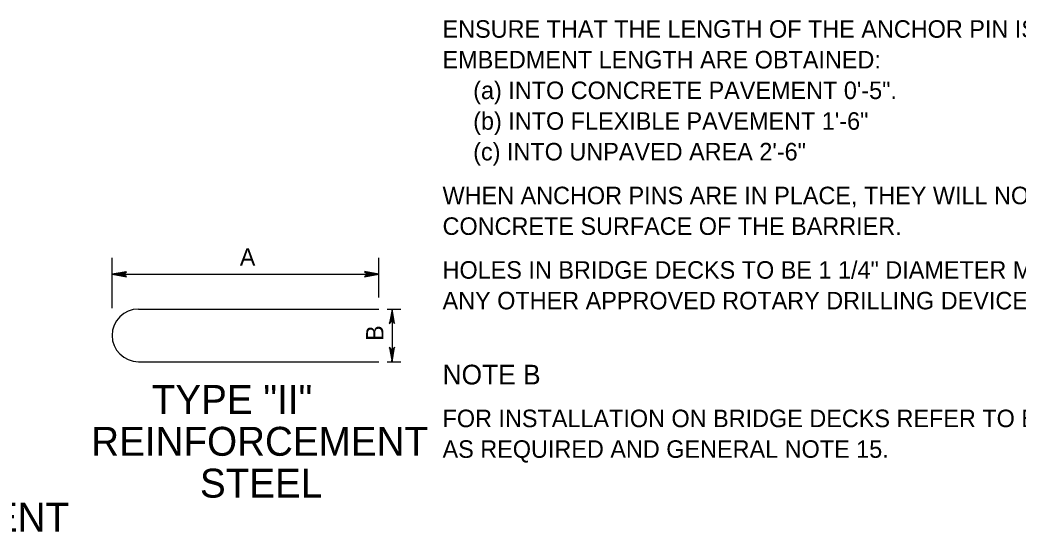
# Model space of a CAD drawing. Extents: x 499883 to 500983, y 499104 to 499764.
# Drawn here: x 500568.6 to 500796.7, y 499313.5 to 499430.4 of the extents above; entities that cross this region are included whole.
import ezdxf

# ---------------------------------------------------------------- set-up
doc = ezdxf.new("R2010")
doc.units = 0
doc.layers.add('24', color=7, linetype='Continuous')
doc.layers.add('5', color=7, linetype='Continuous')

msp = doc.modelspace()

# ---------------------------------------------------------------- linework, layer by layer
at = {"layer": '24'}
for points in [[(500589.68, 499372.4), (500592.96, 499371.82), (500592.18, 499372.4), (500592.94, 499372.97), (500589.68, 499372.4), (500589.9, 499372.41), (500592.87, 499371.87), (500592.12, 499372.41), (500592.81, 499372.93), (500590.02, 499372.42), (500590.13, 499372.4), (500592.67, 499371.95), (500592.1, 499372.41), (500592.68, 499372.85), (500590.18, 499372.4), (500590.29, 499372.42), (500592.51, 499372.02), (500592.08, 499372.4), (500592.52, 499372.8), (500590.6, 499372.42), (500590.79, 499372.42), (500592.34, 499372.1), (500592.04, 499372.39), (500592.37, 499372.72), (500590.82, 499372.4), (500591, 499372.39), (500592.16, 499372.19), (500591.94, 499372.42), (500592.18, 499372.64), (500591.16, 499372.4), (500591.32, 499372.39), (500592.02, 499372.25), (500591.91, 499372.41), (500592.1, 499372.58), (500591.41, 499372.4), (500591.86, 499372.29), (500591.8, 499372.42), (500592, 499372.54), (500591.52, 499372.42), (500591.82, 499372.34), (500591.7, 499372.44), (500591.84, 499372.5), (500591.7, 499372.41), (500591.77, 499372.39)], [(500650.64, 499372.4), (500647.36, 499372.98), (500648.15, 499372.4), (500647.38, 499371.83), (500650.64, 499372.4), (500650.42, 499372.4), (500647.46, 499372.94), (500648.21, 499372.4), (500647.51, 499371.88), (500650.3, 499372.39), (500650.2, 499372.4), (500647.66, 499372.85), (500648.23, 499372.4), (500647.64, 499371.95), (500650.15, 499372.4), (500650.04, 499372.39), (500647.82, 499372.79), (500648.25, 499372.4), (500647.81, 499372), (500649.72, 499372.39), (500649.54, 499372.39), (500647.98, 499372.7), (500648.28, 499372.41), (500647.96, 499372.09), (500649.5, 499372.4), (500649.33, 499372.41), (500648.16, 499372.61), (500648.38, 499372.39), (500648.14, 499372.16), (500649.17, 499372.4), (500649, 499372.42), (500648.3, 499372.55), (500648.42, 499372.4), (500648.22, 499372.22), (500648.92, 499372.4), (500648.46, 499372.51), (500648.53, 499372.39), (500648.32, 499372.26), (500648.8, 499372.39), (500648.5, 499372.46), (500648.63, 499372.36), (500648.48, 499372.3), (500648.63, 499372.4), (500648.55, 499372.41)]]:
    msp.add_lwpolyline(points, dxfattribs=at)
at = {"layer": '5'}
for p, q in [((500589.68, 499364.67), (500589.68, 499376.16)), ((500650.64, 499367.1), (500650.64, 499376.16)), ((500589.68, 499372.4), (500650.64, 499372.4)), ((500595.68, 499364.42), (500650.64, 499364.42)), ((500652.54, 499364.42), (500655.63, 499364.42)), ((500653.64, 499364.42), (500653.64, 499352.43)), ((500595.68, 499352.43), (500650.64, 499352.43)), ((500652.54, 499352.43), (500655.63, 499352.43))]:
    msp.add_line(p, q, dxfattribs=at)
for points in [[(500653.64, 499364.42), (500653.05, 499361.1), (500653.64, 499361.89), (500654.21, 499361.12), (500653.64, 499364.42), (500653.64, 499364.2), (500653.09, 499361.19), (500653.64, 499361.96), (500654.17, 499361.25), (500653.65, 499364.08), (500653.64, 499363.97), (500653.18, 499361.39), (500653.64, 499361.97), (500654.09, 499361.38), (500653.64, 499363.92), (500653.65, 499363.81), (500653.25, 499361.56), (500653.64, 499362), (500654.04, 499361.55), (500653.65, 499363.49), (500653.65, 499363.3), (500653.33, 499361.72), (500653.63, 499362.03), (500653.96, 499361.7), (500653.64, 499363.27), (500653.63, 499363.09), (500653.42, 499361.91), (500653.65, 499362.13), (500653.88, 499361.89), (500653.64, 499362.93), (500653.62, 499362.76), (500653.48, 499362.05), (500653.64, 499362.17), (500653.82, 499361.97), (500653.64, 499362.67), (500653.53, 499362.21), (500653.65, 499362.28), (500653.78, 499362.07), (500653.65, 499362.56), (500653.58, 499362.25), (500653.68, 499362.38), (500653.74, 499362.23), (500653.64, 499362.38), (500653.63, 499362.3)], [(500653.64, 499352.43), (500654.22, 499355.76), (500653.64, 499354.96), (500653.06, 499355.74), (500653.64, 499352.43), (500653.63, 499352.65), (500654.18, 499355.66), (500653.63, 499354.9), (500653.1, 499355.6), (500653.62, 499352.77), (500653.64, 499352.88), (500654.09, 499355.46), (500653.63, 499354.88), (500653.18, 499355.48), (500653.64, 499352.93), (500653.62, 499353.04), (500654.03, 499355.3), (500653.64, 499354.86), (500653.23, 499355.31), (500653.62, 499353.37), (500653.62, 499353.55), (500653.94, 499355.13), (500653.65, 499354.82), (500653.32, 499355.15), (500653.64, 499353.59), (500653.65, 499353.76), (500653.85, 499354.95), (500653.62, 499354.72), (500653.39, 499354.97), (500653.64, 499353.93), (500653.65, 499354.09), (500653.79, 499354.81), (500653.63, 499354.69), (500653.45, 499354.88), (500653.64, 499354.18), (500653.75, 499354.65), (500653.62, 499354.58), (500653.49, 499354.78), (500653.62, 499354.3), (500653.7, 499354.6), (500653.6, 499354.48), (500653.54, 499354.62), (500653.63, 499354.48), (500653.65, 499354.55)]]:
    msp.add_lwpolyline(points, dxfattribs=at)
msp.add_arc((500595.68, 499358.43), 6, 90, 270, dxfattribs=at)

# ---------------------------------------------------------------- texts
for s, height, p in [('ENSURE THAT THE LENGTH OF THE ANCHOR PIN IS SUCH THAT THE FOLLOWING MINIMUM ', 4, (500665.19, 499426.37)), ('EMBEDMENT LENGTH ARE OBTAINED:', 4, (500665.19, 499419.37)), ('(a) INTO CONCRETE PAVEMENT 0\'-5".', 4, (500672.19, 499412.37)), ('(b) INTO FLEXIBLE PAVEMENT 1\'-6"', 4, (500672.19, 499405.37)), ('(c) INTO UNPAVED AREA 2\'-6" ', 4, (500672.19, 499398.37)), ('WHEN ANCHOR PINS ARE IN PLACE, THEY WILL NOT PROJECT ABOVE THE PLANE OF THE', 4, (500665.19, 499388.37)), ('CONCRETE SURFACE OF THE BARRIER.', 4, (500665.19, 499381.37)), ('A', 3.94, (500618.88, 499374.37)), ('HOLES IN BRIDGE DECKS TO BE 1 1/4" DIAMETER MAXIMUM AND MADE WITH A CORE DRILL OR', 4, (500665.19, 499371.37)), ('ANY OTHER APPROVED ROTARY DRILLING DEVICE THAT DOES NOT IMPART AN IMPACT FORCE.', 4, (500665.19, 499364.37)), ('NOTE B', 4.5, (500665.19, 499347.23)), ('TYPE "II" ', 6.6, (500598.74, 499340.51)), ('FOR INSTALLATION ON BRIDGE DECKS REFER TO BRIDGE PLANS FOR NECESSARY MODIFICATIONS', 4, (500665.19, 499337.48)), ('REINFORCEMENT', 6.6001, (500584.9, 499330.95)), ('AS REQUIRED AND GENERAL NOTE 15.', 4, (500665.19, 499330.48)), ('STEEL', 6.6, (500609.75, 499321.4)), ('REINFORCEMENT ', 6.6001, (500502.87, 499313.64))]:
    msp.add_text(s, height=height, dxfattribs=at).set_placement(p)
msp.add_text('B', height=3.94, rotation=90, dxfattribs=at).set_placement((500651.67, 499357.2))

doc.saveas('drawing.dxf')
